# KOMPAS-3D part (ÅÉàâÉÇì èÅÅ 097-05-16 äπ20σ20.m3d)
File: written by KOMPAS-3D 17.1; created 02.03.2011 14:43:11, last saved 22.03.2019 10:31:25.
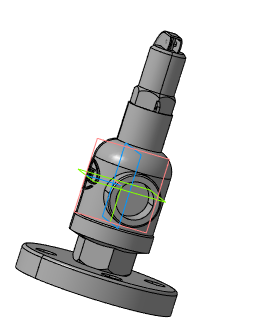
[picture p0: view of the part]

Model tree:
1. Плоскость XY
2. Плоскость ZX
3. Плоскость ZY
4. Ось X
5. Ось Y
6. Ось Z
7. Начало координат
8. Операция без истории:2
